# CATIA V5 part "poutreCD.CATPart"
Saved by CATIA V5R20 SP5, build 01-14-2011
Part number: poutreCD
Bounding box of the stored display mesh (mm): x -1200 to -700, y 1275.242 to 1600.17, z 210.519 to 749.954
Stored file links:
  F:\iao fini\poutreCD.CATPart
  F:\iao fini\iao-finipbgliss.CATProduct
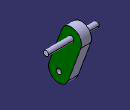
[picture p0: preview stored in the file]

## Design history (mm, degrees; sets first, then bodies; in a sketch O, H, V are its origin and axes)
External parameters (linked from other documents)
  External.rayontrou = 50 mm
  External.epaisseur = 50 mm
  External.epaisseur.1 = 125 mm
Set1
  Plane1 "Plan CD": linked copy from another document
  Point1: linked copy from another document
  Point2: linked copy from another document
Body1 (main body)
  Sketch1 on Plane1, origin (-1050, 0, 0), H (0, 1, 0), V (0, 0, 1)
    circle A1 centre (1500.1993, 649.9838) radius 25
    point P1 (1500.1993, 649.9838)
    circle A2 centre (1375.213, 310.49) radius 25
    point P2 (1375.213, 310.49)
    reference projected point E1 (1500.1993, 649.9838) from Point1
    reference projected point E2 (1375.213, 310.49) from Point2
    arc A3 centre (1500.1993, 649.9838) radius 100 from (1594.0417, 615.4353) to (1406.3569, 684.5323) ccw
    point P3 (1500.1993, 649.9838)
    arc A4 centre (1375.213, 310.49) radius 100 from (1281.3706, 345.0385) to (1469.0554, 275.9415) ccw
    line L1 (1594.0417, 615.4353) -> (1469.0554, 275.9415)
    line L2 (1406.3569, 684.5323) -> (1281.3706, 345.0385)
    radius A2 = 25 {= External.rayontrou *1/2}
    radius A1 = 25 {= External.rayontrou *1/2}
    radius A3 = 100 {= 2*External.rayontrou}
    radius A4 = 100 {= 2*External.rayontrou}
    coincidence: E1 P1, E2 P2
    concentricity: P3 A1, A4 A2
    tangency: L2 A4, L1 A4, A3 L1, A3 L2
  Pad1: profile Sketch1, direction (1, 0, 0), length 100 {= External.epaisseur*2}
  Sketch2 on end face of Pad1, origin (-950, 0, 0), H (0, 1, 0), V (0, 0, 1)
    circle A1 centre (1500.1993, 649.9838) radius 25
    point P1 (1500.1993, 649.9838)
    reference projected point E1 (1500.1993, 649.9838) from Point1
    radius A1 = 25 {= External.rayontrou *1/2}
    coincidence: E1 P1
  Pad2: profile Sketch2, direction (1, 0, 0), length 250 {= 5*External.epaisseur}, mirrored extent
